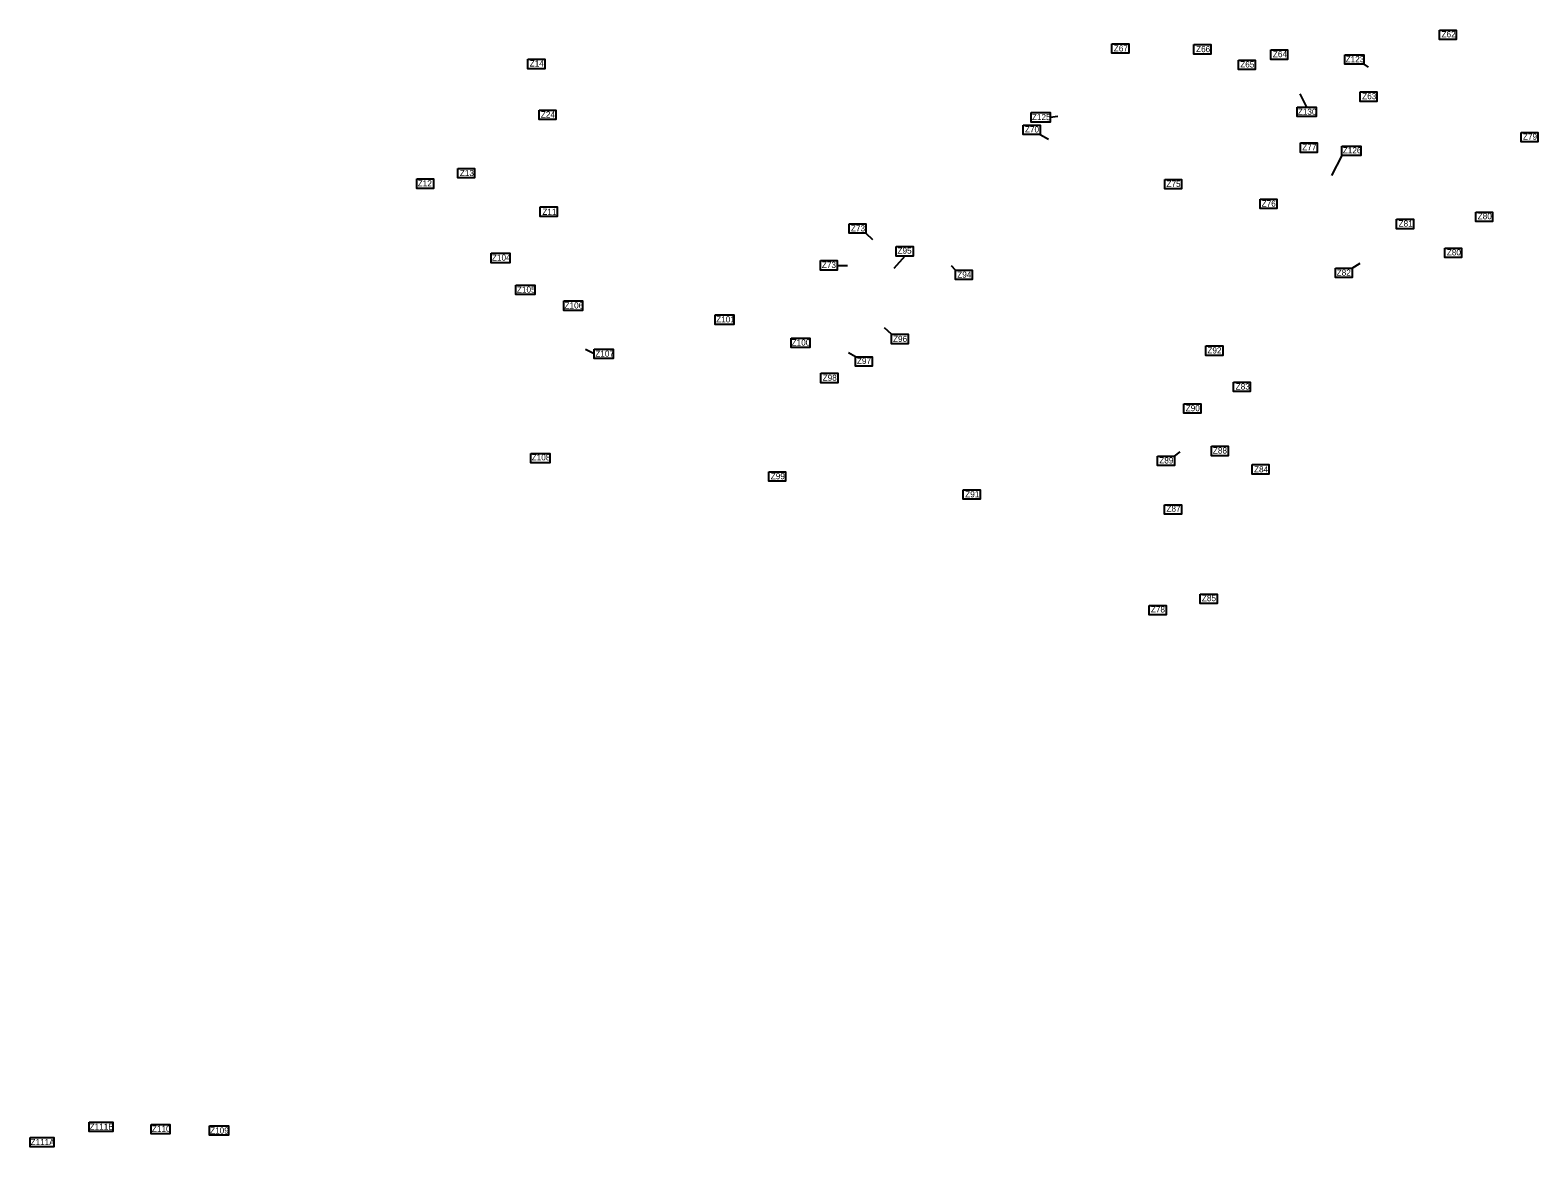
# Model space of a CAD drawing. Extents: x -443483 to -437875, y -1135204 to -1129797.
# Drawn here: x -443483 to -441026, y -1133472 to -1131650 of the extents above; entities that cross this region are included whole.
import ezdxf

# ---------------------------------------------------------------- set-up
doc = ezdxf.new("R2010")
doc.units = 0
doc.layers.add('Vrstva 3', color=7, linetype='Continuous')
doc.layers.add('Vrstva 8', color=7, linetype='Continuous')

msp = doc.modelspace()

# ---------------------------------------------------------------- linework, layer by layer
at = {"layer": 'Vrstva 3'}
for p, q in [((-441837, -1131820.4), (-441823.1, -1131827.9)), ((-442121, -1131981.6), (-442110, -1131991.6)), ((-442167.8, -1132033.9), (-442150.7, -1132034.1)), ((-442057.7, -1132018.8), (-442075.2, -1132039)), ((-441975.1, -1132041.6), (-441981.4, -1132034.6)), ((-441328.2, -1132038.3), (-441315, -1132030.3)), ((-442079.2, -1132146.3), (-442090.7, -1132135.7)), ((-442563.8, -1132178.3), (-442578.2, -1132171.1)), ((-442137.9, -1132182.9), (-442149.2, -1132176.8)), ((-441618.1, -1132344.9), (-441608.8, -1132338.2))]:
    msp.add_line(p, q, dxfattribs=at)
for points in [[(-441186, -1131650.3), (-441158.6, -1131650.3), (-441158.6, -1131665.7), (-441186, -1131665.7)], [(-441719.9, -1131672.7), (-441692.5, -1131672.7), (-441692.5, -1131688.1), (-441719.9, -1131688.1)], [(-441586.1, -1131673.9), (-441558.7, -1131673.9), (-441558.7, -1131689.3), (-441586.1, -1131689.3)], [(-441460.9, -1131682.5), (-441433.5, -1131682.5), (-441433.5, -1131697.9), (-441460.9, -1131697.9)], [(-442671.7, -1131697.8), (-442644.4, -1131697.8), (-442644.4, -1131713.2), (-442671.7, -1131713.2)], [(-441513.5, -1131699.1), (-441486.1, -1131699.1), (-441486.1, -1131714.5), (-441513.5, -1131714.5)], [(-441315.3, -1131751.1), (-441287.9, -1131751.1), (-441287.9, -1131766.5), (-441315.3, -1131766.5)], [(-442653.5, -1131780.7), (-442626.2, -1131780.7), (-442626.2, -1131796.1), (-442653.5, -1131796.1)], [(-441864.3, -1131805), (-441837, -1131805), (-441837, -1131820.4), (-441864.3, -1131820.4)], [(-441412.5, -1131834.2), (-441385.1, -1131834.2), (-441385.1, -1131849.6), (-441412.5, -1131849.6)], [(-441053, -1131817.2), (-441025.6, -1131817.2), (-441025.6, -1131832.6), (-441053, -1131832.6)], [(-442786.3, -1131876), (-442759, -1131876), (-442759, -1131891.4), (-442786.3, -1131891.4)], [(-442853.1, -1131893), (-442825.7, -1131893), (-442825.7, -1131908.4), (-442853.1, -1131908.4)], [(-441633.7, -1131893.9), (-441606.4, -1131893.9), (-441606.4, -1131909.3), (-441633.7, -1131909.3)], [(-442651.8, -1131938.6), (-442624.4, -1131938.6), (-442624.4, -1131954), (-442651.8, -1131954)], [(-441478.3, -1131925.9), (-441450.9, -1131925.9), (-441450.9, -1131941.3), (-441478.3, -1131941.3)], [(-441255.9, -1131958.8), (-441228.5, -1131958.8), (-441228.5, -1131974.2), (-441255.9, -1131974.2)], [(-441126.7, -1131946.9), (-441099.4, -1131946.9), (-441099.4, -1131962.3), (-441126.7, -1131962.3)], [(-442148.4, -1131966.2), (-442121, -1131966.2), (-442121, -1131981.6), (-442148.4, -1131981.6)], [(-442071.4, -1132003.4), (-442044, -1132003.4), (-442044, -1132018.8), (-442071.4, -1132018.8)], [(-441177.4, -1132005.6), (-441150, -1132005.6), (-441150, -1132021), (-441177.4, -1132021)], [(-442731.9, -1132014.2), (-442701.2, -1132014.2), (-442701.2, -1132029.6), (-442731.9, -1132029.6)], [(-442195.1, -1132026.2), (-442167.8, -1132026.2), (-442167.8, -1132041.6), (-442195.1, -1132041.6)], [(-441975.1, -1132041.6), (-441947.7, -1132041.6), (-441947.7, -1132057), (-441975.1, -1132057)], [(-441355.6, -1132038.3), (-441328.2, -1132038.3), (-441328.2, -1132053.7), (-441355.6, -1132053.7)], [(-442691.5, -1132066.2), (-442660.7, -1132066.2), (-442660.7, -1132081.6), (-442691.5, -1132081.6)], [(-442613.5, -1132092), (-442582.8, -1132092), (-442582.8, -1132107.4), (-442613.5, -1132107.4)], [(-442366.7, -1132114.8), (-442336, -1132114.8), (-442336, -1132130.2), (-442366.7, -1132130.2)], [(-442242.9, -1132152.5), (-442212.2, -1132152.5), (-442212.2, -1132167.9), (-442242.9, -1132167.9)], [(-442079.2, -1132146.3), (-442051.8, -1132146.3), (-442051.8, -1132161.7), (-442079.2, -1132161.7)], [(-442563.8, -1132170.6), (-442533.1, -1132170.6), (-442533.1, -1132186), (-442563.8, -1132186)], [(-442137.9, -1132182.9), (-442110.5, -1132182.9), (-442110.5, -1132198.2), (-442137.9, -1132198.2)], [(-441566.6, -1132165.3), (-441539.2, -1132165.3), (-441539.2, -1132180.7), (-441566.6, -1132180.7)], [(-442194.3, -1132209.9), (-442166.9, -1132209.9), (-442166.9, -1132225.3), (-442194.3, -1132225.3)], [(-441521.7, -1132224.2), (-441494.3, -1132224.2), (-441494.3, -1132239.6), (-441521.7, -1132239.6)], [(-441602.6, -1132259.7), (-441575.2, -1132259.7), (-441575.2, -1132275.1), (-441602.6, -1132275.1)], [(-441557.5, -1132329), (-441530.2, -1132329), (-441530.2, -1132344.4), (-441557.5, -1132344.4)], [(-442667.1, -1132340.5), (-442636.3, -1132340.5), (-442636.3, -1132355.9), (-442667.1, -1132355.9)], [(-441645.5, -1132344.9), (-441618.1, -1132344.9), (-441618.1, -1132360.3), (-441645.5, -1132360.3)], [(-442279.2, -1132370.4), (-442251.8, -1132370.4), (-442251.8, -1132385.8), (-442279.2, -1132385.8)], [(-441491.3, -1132358.9), (-441463.9, -1132358.9), (-441463.9, -1132374.3), (-441491.3, -1132374.3)], [(-441962.1, -1132399.9), (-441934.7, -1132399.9), (-441934.7, -1132415.3), (-441962.1, -1132415.3)], [(-441634, -1132424.2), (-441606.6, -1132424.2), (-441606.6, -1132439.6), (-441634, -1132439.6)], [(-441575.8, -1132570.2), (-441548.5, -1132570.2), (-441548.5, -1132585.5), (-441575.8, -1132585.5)], [(-441659, -1132588.5), (-441631.6, -1132588.5), (-441631.6, -1132603.9), (-441659, -1132603.9)], [(-443387, -1133431.3), (-443348.5, -1133431.3), (-443348.5, -1133446.7), (-443387, -1133446.7)], [(-443286.1, -1133434.8), (-443255.3, -1133434.8), (-443255.3, -1133450.2), (-443286.1, -1133450.2)], [(-443190.7, -1133437.1), (-443160, -1133437.1), (-443160, -1133452.5), (-443190.7, -1133452.5)], [(-443483.2, -1133456.1), (-443444.8, -1133456.1), (-443444.8, -1133471.5), (-443483.2, -1133471.5)], [(-443483.2, -1133456.1), (-443444.8, -1133456.1), (-443444.8, -1133471.5), (-443483.2, -1133471.5)], [(-443483.2, -1133456.1), (-443444.8, -1133456.1), (-443444.8, -1133471.5), (-443483.2, -1133471.5)]]:
    msp.add_lwpolyline(points, close=True, dxfattribs=at)
at = {"layer": 'Vrstva 8'}
for p, q in [((-441309.4, -1131706), (-441302.4, -1131710.9)), ((-441402.4, -1131775.9), (-441412.9, -1131754.3)), ((-441820.6, -1131792.4), (-441808, -1131790.5)), ((-441345, -1131854.7), (-441361.9, -1131887.4))]:
    msp.add_line(p, q, dxfattribs=at)
for points in [[(-441340.2, -1131690.6), (-441309.4, -1131690.6), (-441309.4, -1131706), (-441340.2, -1131706)], [(-441851.3, -1131784.7), (-441820.6, -1131784.7), (-441820.6, -1131800.1), (-441851.3, -1131800.1)], [(-441417.8, -1131775.9), (-441387.1, -1131775.9), (-441387.1, -1131791.3), (-441417.8, -1131791.3)], [(-441345, -1131839.3), (-441314.2, -1131839.3), (-441314.2, -1131854.7), (-441345, -1131854.7)]]:
    msp.add_lwpolyline(points, close=True, dxfattribs=at)

# ---------------------------------------------------------------- texts
at = {"layer": 'Vrstva 3'}
for s, p in [('Z62', (-441182.6, -1131662.1)), ('Z67', (-441716.9, -1131685)), ('Z66', (-441582.7, -1131686.2)), ('Z64', (-441457.5, -1131694.4)), ('Z14', (-442668.9, -1131709.6)), ('Z65', (-441510.7, -1131711.2)), ('Z63', (-441311.9, -1131762.9)), ('Z24', (-442650.7, -1131792.9)), ('Z70', (-441861.7, -1131817.2)), ('Z77', (-441409.6, -1131846.1)), ('Z79', (-441049.9, -1131829)), ('Z13', (-442782.8, -1131888.3)), ('Z12', (-442851.5, -1131905.2)), ('Z75', (-441631, -1131906)), ('Z76', (-441475.8, -1131938.1)), ('Z11', (-442648.3, -1131951.5)), ('Z81', (-441252.6, -1131970.7)), ('Z80', (-441123.6, -1131958.7)), ('Z73', (-442145.3, -1131978.4)), ('Z95', (-442069.4, -1132014.9)), ('Z80', (-441174, -1132017.7)), ('Z104', (-442730.5, -1132026.2)), ('Z73', (-442192.7, -1132038.1)), ('Z94', (-441972, -1132054)), ('Z82', (-441353.5, -1132050.7)), ('Z105', (-442689.8, -1132078.4)), ('Z106', (-442612.2, -1132104.3)), ('Z101', (-442365, -1132127)), ('Z100', (-442242, -1132164.7)), ('Z96', (-442076.7, -1132158.8)), ('Z107', (-442562, -1132182.9)), ('Z92', (-441564.3, -1132177.6)), ('Z97', (-442135.5, -1132194.7)), ('Z98', (-442191.4, -1132222.2)), ('Z83', (-441518.1, -1132236.4)), ('Z90', (-441599.6, -1132271.8)), ('Z88', (-441555.3, -1132340.8)), ('Z108', (-442665.7, -1132352)), ('Z89', (-441642.7, -1132357)), ('Z99', (-442276, -1132382.7)), ('Z84', (-441488.2, -1132371.5)), ('Z91', (-441959, -1132412.2)), ('Z87', (-441631, -1132435.7)), ('Z85', (-441573.2, -1132581.6)), ('Z78', (-441656.4, -1132600)), ('Z111B', (-443386.3, -1133443.6)), ('Z110', (-443284.8, -1133447.1)), ('Z111A', (-443482.6, -1133468.7)), ('Z109', (-443189.9, -1133449.9))]:
    msp.add_text(s, height=10, dxfattribs=at).set_placement(p)
at = {"layer": 'Vrstva 8'}
for s, p in [('Z123', (-441338.9, -1131702.6)), ('Z125', (-441850.3, -1131797.1)), ('Z130', (-441416.9, -1131788.4)), ('Z126', (-441343.6, -1131851.3))]:
    msp.add_text(s, height=10, dxfattribs=at).set_placement(p)

doc.saveas('drawing.dxf')
